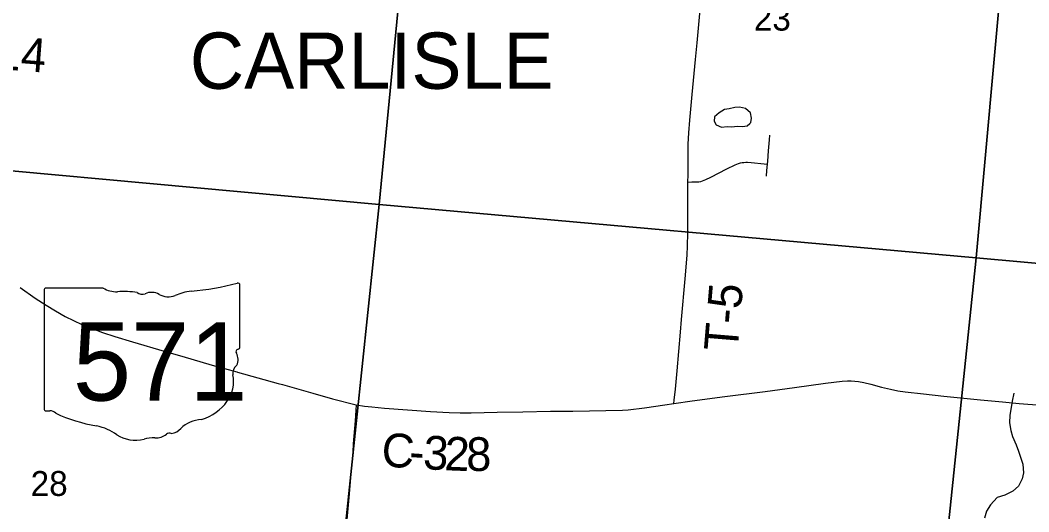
# Model space of a CAD drawing. Extents: x 0 to 1134, y 0 to 440.
# Drawn here: x 836.243 to 837.941, y 363.355 to 364.182 of the extents above; entities that cross this region are included whole.
import ezdxf

# ---------------------------------------------------------------- set-up
doc = ezdxf.new("R2010")
doc.units = 0
for name, color, linetype in [('GM_X_Corporation_Text', 7, 'Continuous'), ('GM_X_County_Road', 7, 'Continuous'), ('GM_X_County_Road_Text', 7, 'Continuous'), ('GM_X_Minor_Lake', 7, 'Continuous'), ('GM_X_Minor_River', 7, 'Continuous'), ('GM_X_Section', 7, 'Continuous'), ('GM_X_Section_Text', 7, 'Continuous'), ('GM_X_State_Location', 7, 'Continuous'), ('GM_X_State_Route', 7, 'Continuous'), ('GM_X_State_Shield', 7, 'Continuous'), ('GM_X_Township_Road', 7, 'Continuous'), ('GM_X_Township_Road_Text', 7, 'Continuous')]:
    doc.layers.add(name, color=color, linetype=linetype)

msp = doc.modelspace()

# ---------------------------------------------------------------- linework, layer by layer
at = {"layer": 'GM_X_County_Road'}
for points in [[(837.3436, 363.537), (837.3742, 363.5414), (837.4296, 363.5489), (837.4974, 363.5575), (837.5467, 363.5643), (837.599, 363.5712), (837.6267, 363.5746), (837.636, 363.5753), (837.6421, 363.5753), (837.6482, 363.5749), (837.6543, 363.5742), (837.6634, 363.5724), (837.6754, 363.5695), (837.6934, 363.5647), (837.7085, 363.561), (837.7207, 363.5585), (837.7331, 363.5566), (837.764, 363.5531), (837.798, 363.5496), (837.8597, 363.5435), (837.8968, 363.54), (837.9247, 363.5373), (837.9618, 363.534)], [(836.8087, 363.5348), (836.8225, 363.5326), (836.8349, 363.5312), (836.8566, 363.5294), (836.934, 363.5238), (836.9651, 363.5221), (836.9838, 363.5215), (837.0024, 363.5215), (837.0459, 363.5224), (837.0894, 363.5233), (837.136, 363.5239), (837.1733, 363.5244), (837.2572, 363.5256), (837.2665, 363.5263), (837.2942, 363.53), (837.3281, 363.5348), (837.3436, 363.537)]]:
    msp.add_lwpolyline(points, dxfattribs=at)
at = {"layer": 'GM_X_Minor_Lake'}
for points in [[(837.4714, 364.0084), (837.4731, 364.01), (837.4743, 364.0176), (837.4726, 364.0263), (837.4643, 364.034), (837.4541, 364.0361), (837.4461, 364.0354), (837.4366, 364.0332), (837.4289, 364.0318), (837.4198, 364.0266), (837.4121, 364.0198), (837.4116, 364.0122)], [(837.4116, 364.0122), (837.4149, 364.0061), (837.424, 364.0022), (837.4331, 364.0032), (837.4407, 364.0027), (837.4506, 364.0038), (837.459, 364.0037), (837.467, 364.0043), (837.4714, 364.0084)]]:
    msp.add_lwpolyline(points, dxfattribs=at)
at = {"layer": 'GM_X_Minor_River'}
msp.add_lwpolyline([(837.9159, 363.5542), (837.9134, 363.541), (837.911, 363.5269), (837.9093, 363.5174), (837.9088, 363.5045), (837.9109, 363.4916), (837.9138, 363.4816), (837.9201, 363.4675), (837.9237, 363.4568), (837.9274, 363.4469), (837.9311, 363.4347), (837.9324, 363.4206), (837.93, 363.41), (837.9238, 363.3979), (837.9142, 363.3893), (837.9008, 363.3826), (837.8878, 363.3786), (837.8766, 363.3665), (837.8697, 363.3556), (837.8665, 363.3439)], dxfattribs=at)
at = {"layer": 'GM_X_Section'}
for points in [[(835.9355, 364.9781), (836.9458, 364.8879), (836.8475, 363.8721), (835.8418, 363.9641)], [(836.9458, 364.8879), (837.9445, 364.7986), (837.8523, 363.7821), (836.8475, 363.8721)], [(837.9445, 364.7986), (838.9444, 364.6922), (838.8532, 363.692), (837.8523, 363.7821)], [(835.8418, 363.9641), (836.8475, 363.8721), (836.7427, 362.8719), (835.7429, 362.9536)], [(836.8475, 363.8721), (837.8523, 363.7821), (837.7459, 362.7561), (836.7427, 362.8719)], [(837.8523, 363.7821), (838.8532, 363.692), (838.749, 362.6588), (837.7459, 362.7561)]]:
    msp.add_lwpolyline(points, close=True, dxfattribs=at)
at = {"layer": 'GM_X_State_Route'}
for points in [[(836.2428, 363.7322), (836.2683, 363.7145), (836.2866, 363.7026), (836.3025, 363.6929), (836.3188, 363.6838), (836.3326, 363.6768), (836.3468, 363.6703), (836.3641, 363.6632), (836.3815, 363.6566), (836.4022, 363.6498), (836.432, 363.6409), (836.4856, 363.6252), (836.5154, 363.6166), (836.5661, 363.6018), (836.608, 363.5903), (836.609, 363.59)], [(836.609, 363.59), (836.6775, 363.571), (836.6845, 363.569), (836.7358, 363.5542), (836.7691, 363.5448), (836.8087, 363.5348)], [(836.8087, 363.5348), (836.8068, 363.5078), (836.8059, 363.495), (836.8039, 363.4693), (836.8029, 363.4559), (836.8005, 363.4253), (836.7966, 363.3791), (836.7921, 363.3292)]]:
    msp.add_lwpolyline(points, dxfattribs=at)
at = {"layer": 'GM_X_State_Shield'}
for p, q in [((836.6127, 363.6318), (836.6127, 363.7365)), ((836.2832, 363.7281), (836.2832, 363.5279)), ((836.3829, 363.7315), (836.2864, 363.7315)), ((836.6127, 363.6318), (836.6127, 363.6318))]:
    msp.add_line(p, q, dxfattribs=at)
for centre, major_axis, start_param, end_param in [((836.4953, 364.0043), (0.3495, 0), 4.814394, 5.042369), ((836.6091, 363.7369), (0.00367, 0), 6.141152, 7.989035), ((836.2869, 363.7285), (0.00382, 0), 1.712693, 3.28349), ((836.4059, 363.7547), (0.037, 0), 4.042523, 4.731795), ((836.4182, 363.6192), (0.133, 0), 1.404758, 1.657858), ((836.4484, 363.7295), (0.0107, 0), 3.836095, 5.185415), ((836.4641, 363.7064), (0.0222, 0), 0.950623, 2.079405), ((836.4927, 363.7381), (0.0267, 0), 4.081561, 5.145723), ((836.5399, 363.6704), (0.0703, 0), 1.699011, 2.107814), ((836.6119, 363.6241), (0.00568, 0), 1.883978, 3.671073), ((836.5758, 363.6109), (0.0341, 0), 5.934695, 6.695948), ((836.6088, 363.6314), (0.00393, 0), 5.05454, 6.418171), ((836.6259, 363.588), (0.0248, 0), 2.387724, 3.262537), ((836.5149, 363.5746), (0.0874, 0), 5.101752, 6.440018), ((836.287, 363.5275), (0.00385, 0), 3.00124, 4.508301), ((836.2875, 363.548), (0.0294, 0), 4.665946, 4.897461), ((836.2936, 363.5164), (0.0106, 0), 0.519207, 1.627899), ((836.4274, 363.6962), (0.2524, 0), 4.195997, 4.488961), ((836.3521, 363.438), (0.079, 0), 0.823519, 1.323587), ((836.5518, 363.4718), (0.0479, 0), 1.647645, 2.488434), ((836.4375, 363.5154), (0.0501, 0), 4.026481, 4.996735), ((836.4702, 363.5004), (0.0267, 0), 4.691044, 5.507374), ((836.4943, 363.481), (0.00752, 0), 1.147584, 2.315152), ((836.4911, 363.5085), (0.0282, 0), 4.937069, 5.64225), ((836.4665, 363.4462), (0.0412, 0), 1.495662, 1.94098)]:
    msp.add_ellipse(centre, major_axis=major_axis, ratio=0.8, start_param=start_param, end_param=end_param, dxfattribs=at)
at = {"layer": 'GM_X_Township_Road'}
for points in [[(837.3672, 363.9099), (837.3675, 363.9223), (837.3674, 363.9272), (837.3679, 363.9489), (837.3679, 363.9738), (837.3686, 363.9925), (837.3703, 364.0142), (837.3745, 364.0575), (837.3801, 364.1163), (837.3828, 364.1442), (837.3872, 364.1937), (837.3904, 364.2278), (837.3934, 364.2618), (837.3982, 364.3176), (837.3998, 364.3355)], [(837.5014, 363.9402), (837.5019, 363.945), (837.5031, 363.9626), (837.5047, 363.981), (837.5052, 363.9886)], [(837.3672, 363.9099), (837.374, 363.9101), (837.3856, 363.9105), (837.3887, 363.911), (837.3916, 363.9118), (837.3974, 363.914), (837.4057, 363.918), (837.4328, 363.9322), (837.4468, 363.9388), (837.4525, 363.9411), (837.4555, 363.942), (837.4585, 363.9427), (837.4615, 363.9431), (837.4646, 363.9434), (837.4677, 363.9434), (837.4739, 363.943), (837.4955, 363.9408), (837.5014, 363.9402)], [(837.4995, 363.9197), (837.5003, 363.9294), (837.5014, 363.9402)], [(837.3436, 363.537), (837.3442, 363.5428), (837.3462, 363.5613), (837.349, 363.5922), (837.3546, 363.6571), (837.3564, 363.6787), (837.3625, 363.7467), (837.366, 363.7869), (837.3668, 363.8023), (837.3672, 363.824), (837.367, 363.8519), (837.3669, 363.8798), (837.3669, 363.8914), (837.3672, 363.9099)]]:
    msp.add_lwpolyline(points, dxfattribs=at)

# ---------------------------------------------------------------- texts
at = {"layer": 'GM_X_Corporation_Text'}
msp.add_text('CARLISLE', height=0.0947, rotation=0, dxfattribs=at).set_placement((836.5286, 364.0669))
at = {"layer": 'GM_X_County_Road_Text'}
for s, height, rotation, p in [('C-314', 0.05682, 355.6397, (836.0784, 364.1098)), ('C', 0.0568, 356.2778, (836.8501, 363.4314)), ('3', 0.0568, 356.8308, (836.9205, 363.4268)), ('2', 0.0568, 357.7752, (836.9565, 363.4248)), ('8', 0.0568, 0.1887, (836.9941, 363.4234)), ('-', 0.0568, 356.4033, (836.8968, 363.4283))]:
    msp.add_text(s, height=height, rotation=rotation, dxfattribs=at).set_placement(p)
at = {"layer": 'GM_X_Section_Text'}
for s, p in [('23', (837.4782, 364.1649)), ('28', (836.2607, 363.3815))]:
    msp.add_text(s, height=0.04186, rotation=0, dxfattribs=at).set_placement(p)
at = {"layer": 'GM_X_State_Location'}
msp.add_text('571', height=0.000189, rotation=0, dxfattribs=at).set_placement((836.3774, 363.6009))
for s in ['s', 'r']:
    msp.add_text(s, height=0.000189, dxfattribs=at).set_placement((836.4442, 363.6147))
at = {"layer": 'GM_X_State_Shield'}
msp.add_text('571', height=0.13184, dxfattribs=at).set_placement((836.3317, 363.542))
at = {"layer": 'GM_X_Township_Road_Text'}
msp.add_text('T-5', height=0.05682, rotation=85.226, dxfattribs=at).set_placement((837.4507, 363.6235))

doc.saveas('drawing.dxf')
